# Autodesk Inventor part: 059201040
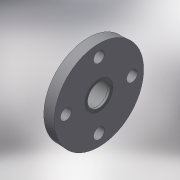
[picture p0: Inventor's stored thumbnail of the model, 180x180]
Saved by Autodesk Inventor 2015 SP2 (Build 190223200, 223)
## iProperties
Created: 2017-10
Part Number: 059201040
Material: Generic
Description: PLASSON THR. FIXED FLANGE PVC 4"
Document SubType Name: Modeling
Designer: KIM
Density: 1 g/cm^3
Appearance: Default
Author: KIM
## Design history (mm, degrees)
derived "059201.ipt"
feature "Solid1::059201.ipt"
tag "TaggingFeature1"
body "Solid1"
other parameters: "d0" = 64, "d3" = 217.8, "d14" = 18, "d16" = 64, "d17" = 0, "d19" = 360 deg, "d22" = 110.072, "d23" = 104.5684, "d25" = 1.10072, "d26" = 1.1, "d27" = 1.1, "d28" = 1.1, "d29" = 1.1, "d30" = 1.1, "d31" = 1.1, "d32" = 0.44, "d33" = 0, "d34" = 22, "d35" = 132.0864, "H_" = 64, "S_" = 18, "G_" = 110.072, "H_1" = 22
